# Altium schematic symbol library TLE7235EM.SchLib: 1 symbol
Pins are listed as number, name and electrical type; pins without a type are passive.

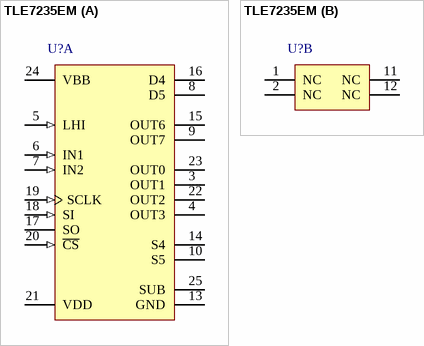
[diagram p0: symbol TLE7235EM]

## TLE7235EM
designator U?
SPI Driver for Enhanced Relay Control, 10 uA Quiescent Current, 3 to 5.5 V VDD, -40 to 150 degC, PG-SSOP-24-4, Reel, Green; Manufacturer: Infineon; PartNumber: TLE7235EM; Channels: 8; Configurable channels: 2; Cranking mode: FALSE; Daisy-chain capability: TRUE; ID nom: 350 mA; ID(lim) (min): 0.5 A; Open Load Detection: off; Overcurrent limitation or shutdown: Shutdown; Quiescent Current (max): 10 uA; RDS (on) (max): 1.9 Ohm; RDS (on) (typ): 0.9 Ohm; SPI: 8 Bit; VDD: 3 - 5.5 V; VDS(CL): 41 - 52 V
footprint INF-PG-SSOP-24-4_N (SOP, 24-Leads, Body 8.65x3.9mm, Pitch 0.65mm, Thermal Pad 6.65x2.9mm, IPC Medium Density)
footprint INF-PG-SSOP-24-4_L (SOP, 24-Leads, Body 8.65x3.9mm, Pitch 0.65mm, Thermal Pad 6.65x2.9mm, IPC High Density)
footprint INF-PG-SSOP-24-4_M (SOP, 24-Leads, Body 8.65x3.9mm, Pitch 0.65mm, Thermal Pad 6.65x2.9mm, IPC Low Density)
part A pins: 3 OUT1 (power) "Source of high side power transistor channel 1", 4 OUT3 (power) "Source of high side power transistor channel 3", 5 LHI (in) "Limp home activation input pin (pull down)", 6 IN1 (in) "Input multiplexer input 1 pin (pull down)", 7 IN2 (in) "Input multiplexer input 2 pin (pull down)", 8 D5 (power) "Drain of auto configuring power transistor 5", 9 OUT7 (power) "Drain of low side power transistor channel 7", 10 S5 (power) "Source of auto configuring power transistor 5", 13 GND (power) "Digital, analog and power ground", 14 S4 (power) "Source of auto configuring power transistor 4", 15 OUT6 (power) "Drain of low side power transistor channel 6", 16 D4 (power) "Drain of auto configuring power transistor 4", 17 SO (hiz) "Serial data out", 18 SI (in) "Serial data in", 19 SCLK (in) "Serial clock", 20 ~{CS} (in) "SPI Chip select (pull up)", 21 VDD (power) "Digital power supply", 22 OUT2 (power) "Source of high side power transistor channel 2", 23 OUT0 (power) "Source of high side power transistor channel 0", 24 VBB (power) "Power supply", 25 SUB "Substrate pins for thermal connection. To enable reverse polarity protection these pins must be floating"
part B pins: 1 NC "not connected", 2 NC "not connected", 11 NC "not connected", 12 NC "not connected"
